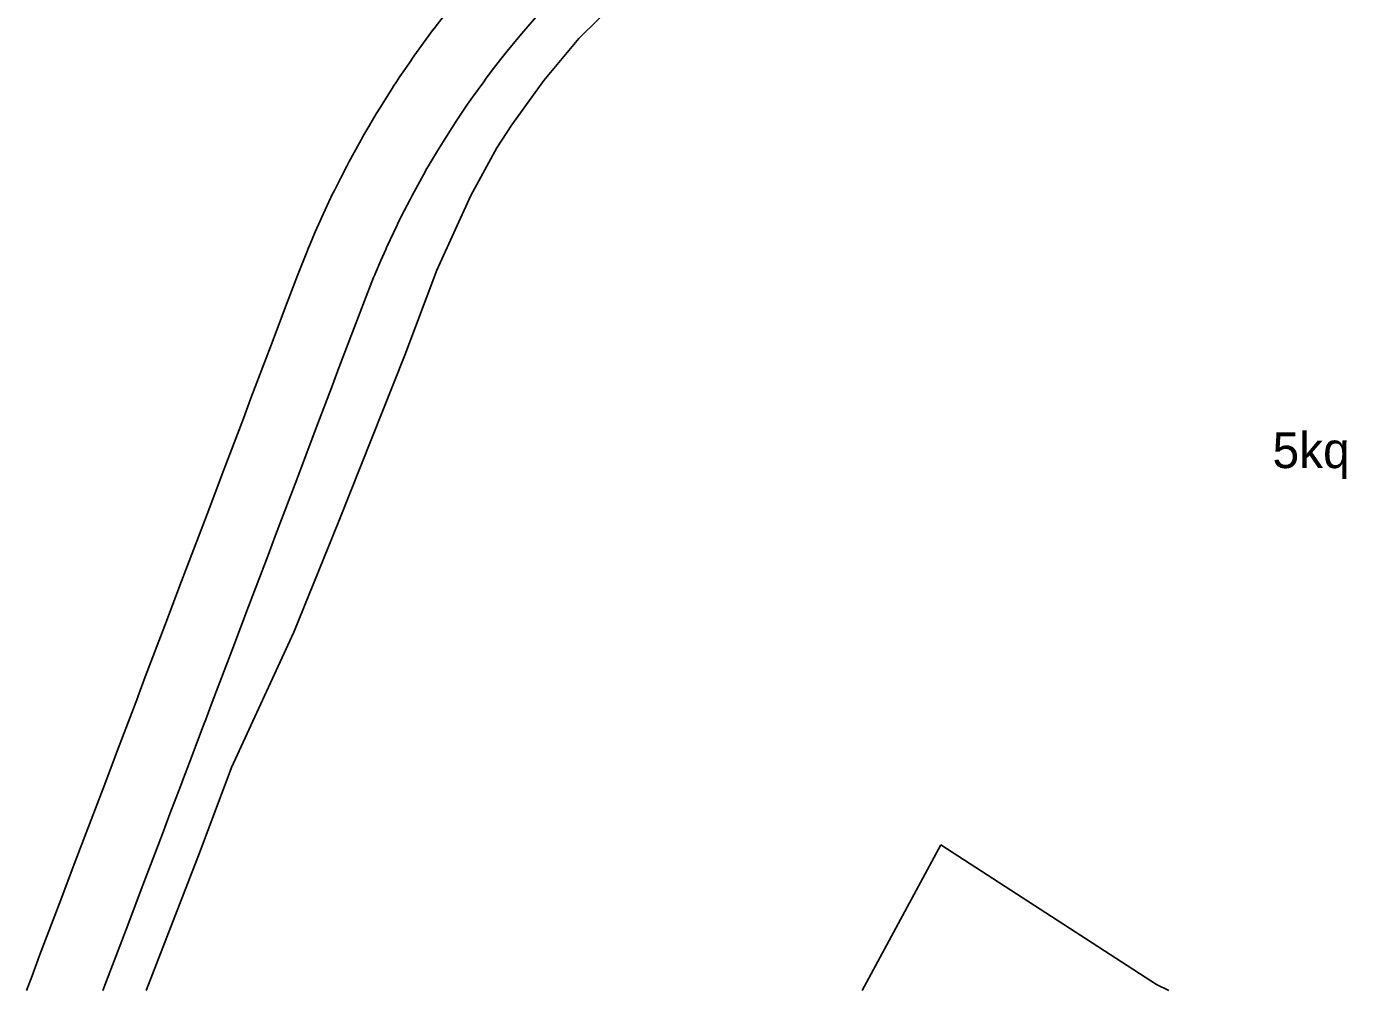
# Model space of a CAD drawing. Extents: x 702630 to 703245, y 6205279 to 6205714.
# Drawn here: x 702685.5 to 702906.9, y 6205279.5 to 6205441.3 of the extents above; entities that cross this region are included whole.
import ezdxf

# ---------------------------------------------------------------- set-up
doc = ezdxf.new("R2010")
doc.units = 0
for name, color, linetype in [('Matrikelnummer', 7, 'Continuous'), ('Matrikelnummer punkt', 7, 'Continuous'), ('Matrikelskel Almindeligt', 7, 'Continuous'), ('Optaget vej', 7, 'Continuous')]:
    doc.layers.add(name, color=color, linetype=linetype)

msp = doc.modelspace()

# ---------------------------------------------------------------- linework, layer by layer
at = {"layer": 'Matrikelnummer punkt'}
msp.add_line((702899.16, 6205370.18), (702899.16, 6205370.18), dxfattribs=at)
at = {"layer": 'Matrikelskel Almindeligt'}
for p, q in [((702778.15, 6205439.27), (702784.67, 6205445.7)), ((702772.28, 6205432.23), (702778.15, 6205439.27)), ((702766.87, 6205424.8), (702772.28, 6205432.23)), ((702764.4, 6205420.94), (702766.87, 6205424.8)), ((702760, 6205412.91), (702764.4, 6205420.94)), ((702754.34, 6205400.41), (702760, 6205412.91)), ((702748.98, 6205386.15), (702754.34, 6205400.41)), ((702737.87, 6205358.26), (702748.98, 6205386.15)), ((702730.33, 6205339.62), (702737.87, 6205358.26)), ((702719.9, 6205316.91), (702730.33, 6205339.62)), ((702714.61, 6205302.92), (702719.9, 6205316.91)), ((702838.86, 6205303.96), (702825.64, 6205279.5)), ((702838.86, 6205303.96), (702875.02, 6205280.5)), ((702705.59, 6205279.5), (702714.61, 6205302.92)), ((702877.07, 6205279.5), (702875.02, 6205280.5))]:
    msp.add_line(p, q, dxfattribs=at)
at = {"layer": 'Optaget vej'}
for points in [[(702755.56, 6205443.13), (702753.89, 6205440.96), (702753.56, 6205440.54), (702752.98, 6205439.75), (702752.52, 6205439.13), (702750.49, 6205436.31), (702749.6, 6205435.04), (702748.14, 6205432.89), (702747.55, 6205432), (702747.05, 6205431.24), (702746.81, 6205430.86), (702744.75, 6205427.59), (702744.14, 6205426.6), (702742.89, 6205424.49), (702742.09, 6205423.1), (702741.67, 6205422.37), (702741.61, 6205422.26), (702739.57, 6205418.53), (702739.2, 6205417.84), (702738.14, 6205415.79), (702737.19, 6205413.88), (702736.94, 6205413.36), (702736.85, 6205413.18), (702734.96, 6205409.16), (702734.8, 6205408.8), (702733.93, 6205406.82), (702732.89, 6205404.37), (702732.81, 6205404.19), (702732.61, 6205403.71), (702730.96, 6205399.52), (702730.23, 6205397.6), (702728.96, 6205394.23), (702726.69, 6205388.25), (702725.41, 6205384.87), (702723.15, 6205378.9), (702721.87, 6205375.52), (702719.6, 6205369.54), (702718.33, 6205366.17), (702716.06, 6205360.19), (702714.78, 6205356.82), (702712.52, 6205350.84), (702711.24, 6205347.46), (702708.97, 6205341.49), (702707.7, 6205338.11), (702705.43, 6205332.13), (702704.17, 6205328.81), (702704.15, 6205328.76), (702701.89, 6205322.78), (702700.61, 6205319.41), (702700.14, 6205318.18), (702698.34, 6205313.43), (702697.07, 6205310.05), (702694.8, 6205304.08), (702693.52, 6205300.7), (702691.26, 6205294.73), (702689.98, 6205291.35), (702687.71, 6205285.37), (702686.44, 6205282), (702685.49, 6205279.5)], [(702770.98, 6205442.89), (702769.22, 6205440.88), (702769.22, 6205440.87), (702768.59, 6205440.13), (702767.94, 6205439.35), (702766.13, 6205437.14), (702765.01, 6205435.73), (702763.45, 6205433.72), (702763.15, 6205433.32), (702762.61, 6205432.59), (702762.18, 6205432.02), (702760.3, 6205429.4), (702759.48, 6205428.22), (702758.12, 6205426.23), (702757.58, 6205425.4), (702757.11, 6205424.69), (702756.89, 6205424.34), (702754.97, 6205421.31), (702754.41, 6205420.39), (702753.25, 6205418.43), (702752.5, 6205417.15), (702752.12, 6205416.46), (702752.06, 6205416.36), (702750.17, 6205412.9), (702749.83, 6205412.27), (702748.85, 6205410.36), (702747.96, 6205408.59), (702747.73, 6205408.11), (702747.65, 6205407.94), (702745.9, 6205404.21), (702745.75, 6205403.88), (702744.93, 6205402.04), (702743.97, 6205399.77), (702743.9, 6205399.6), (702743.72, 6205399.15), (702742.18, 6205395.26), (702741.46, 6205393.35), (702740.18, 6205389.98), (702737.91, 6205384), (702736.64, 6205380.62), (702734.37, 6205374.65), (702733.09, 6205371.27), (702730.83, 6205365.29), (702729.55, 6205361.92), (702727.28, 6205355.94), (702726.01, 6205352.57), (702723.74, 6205346.59), (702722.46, 6205343.21), (702720.2, 6205337.24), (702718.92, 6205333.86), (702716.65, 6205327.88), (702715.39, 6205324.55), (702715.38, 6205324.51), (702713.11, 6205318.53), (702711.83, 6205315.16), (702711.36, 6205313.92), (702709.57, 6205309.18), (702708.29, 6205305.8), (702706.02, 6205299.83), (702704.74, 6205296.45), (702702.48, 6205290.47), (702701.2, 6205287.1), (702698.94, 6205281.12), (702698.32, 6205279.5)]]:
    msp.add_lwpolyline(points, dxfattribs=at)

# ---------------------------------------------------------------- texts
at = {"layer": 'Matrikelnummer'}
msp.add_text('5kq', height=6, dxfattribs=at).set_placement((702894.47, 6205367.18))

doc.saveas('drawing.dxf')
